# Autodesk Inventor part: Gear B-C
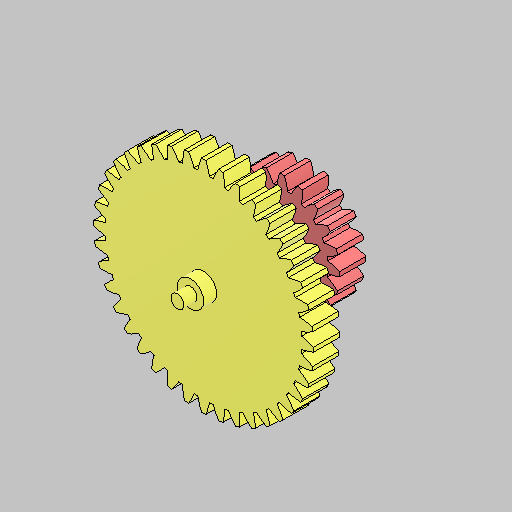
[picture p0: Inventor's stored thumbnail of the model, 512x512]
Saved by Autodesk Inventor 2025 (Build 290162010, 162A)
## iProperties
Created: 2024-10
Part Number: Gear B-C
Material: Generic
Document SubType Name: Modeling
Designer: Dennis
Density: 1 g/cm^3
Appearance: Default
Mass: 64.9746 g
Surface Area: 210.223 cm^2
Volume: 64.9746 cm^3
Author: Dennis
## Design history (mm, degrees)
sketch "Sketch1"
  geometry: L1 (0, 30)-(0, -30); L2 (0, -30)-(2.5, -30); L3 (2.5, -30)-(2.5, -25); L4 (2.5, -25)-(5, -25); L5 (5, -25)-(5, -20); L6 (5, -20)-(22, -20); L7 (22, -20)-(22, -10); L8 (22, -10)-(5, -10); L9 (5, -10)-(5, 10); L10 (5, 10)-(42, 10); L11 (42, 10)-(42, 20); L12 (42, 20)-(5, 20); L13 (5, 20)-(5, 25); L14 (5, 25)-(2.5, 25); L15 (2.5, 25)-(2.5, 30); L16 (2.5, 30)-(0, 30); 2 further points
  constraints: 32 end point, 12 perpendicular, 4 point on line, 3 equal length, 1 coincident, 1 horizontal, 1 midpoint, 1 vertical
  dimensions: "d1" = 10 diameter of L5 L1; "d2" = 5 diameter of L3 L1; "d3" = 44 diameter of L7 L1; "d4" = 84 diameter of L11 L1; "d5" = 5 distance of L2.end L3.end; "d6" = 60 distance of L1.start L1.end; "d7" = 10 distance of L10.end L11.end; "d8" = 5 distance of L4.end L5.end; "d9" = 10 diameter of L9 L1
revolve "Revolution1" sketch "Sketch1" stored, may be unused: angle "d10" = 90 deg
sketch "Sketch2"
  geometry: C1 r 40 at (0, 0); 1 further point
  constraints: 1 centre point, 1 coincident
  dimensions: "d11" = 80 diameter of C1
extrude_surface "ExtrusionSrf1" sketch "Sketch2" dims "d12" = 10, "d13" = 0
sketch "Sketch3"
  geometry: C1 r 20 at (0, 0); 1 further point
  constraints: 1 centre point, 1 coincident
  dimensions: "d14" = 40 diameter of C1
extrude_surface "ExtrusionSrf2" sketch "Sketch3" dims "d15" = 10, "d16" = 0
node "Spur Gear Teeth1"
node "Spur Gear Teeth2"
body "Solid1"
body "Srf1"
body "Srf2"
feature "Spur Gear2"
feature "Spur Gear1"
